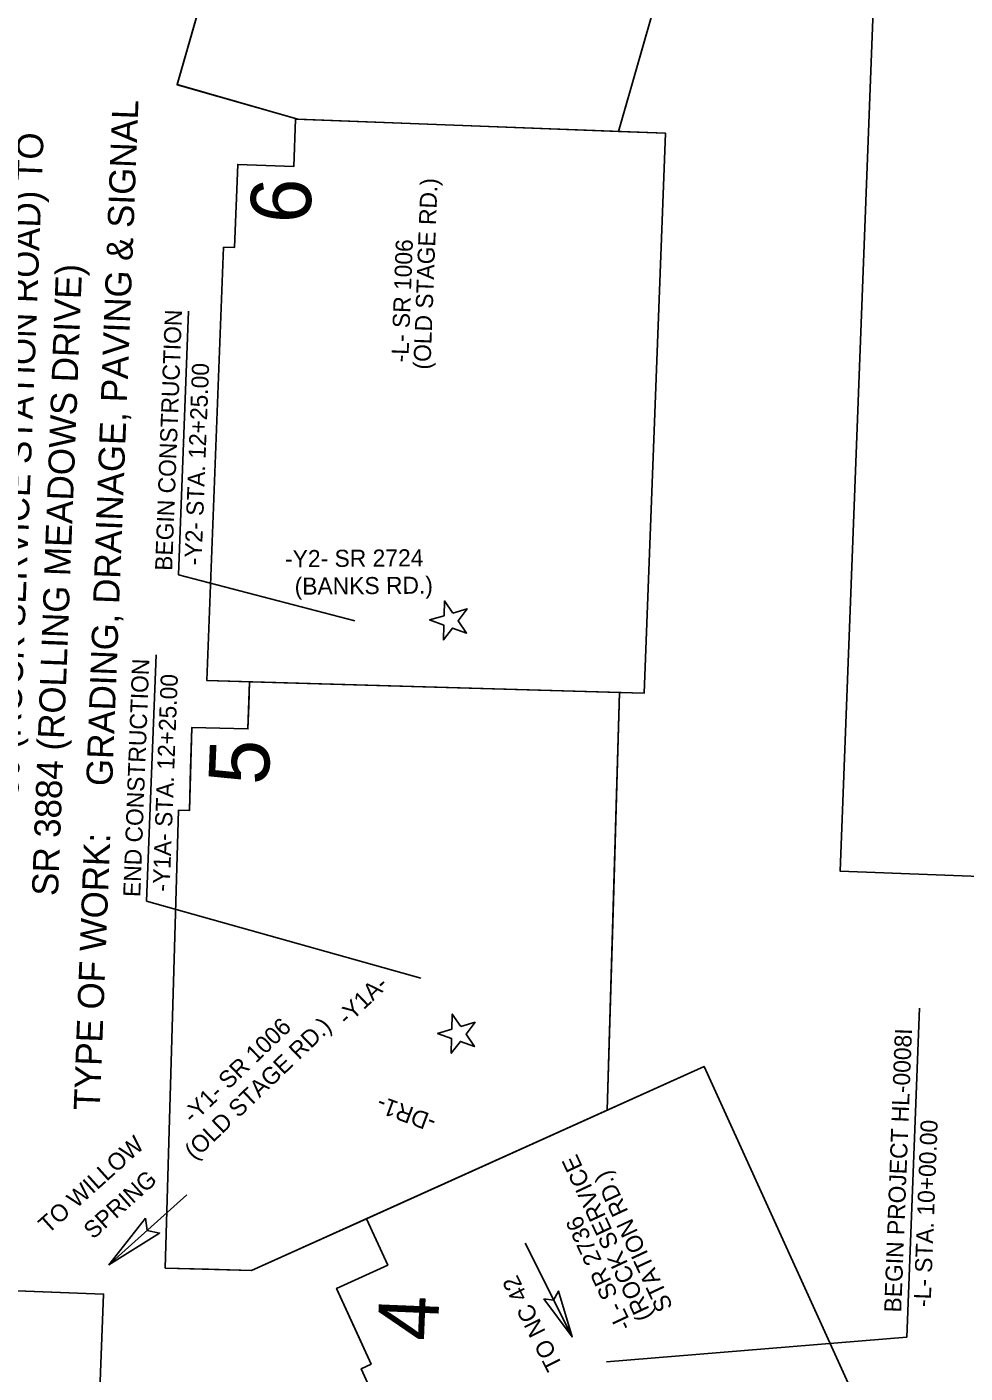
# Model space of a CAD drawing. Extents: x 1654773 to 2116434, y 680831 to 888488.
# Drawn here: x 2096697 to 2098950, y 685073 to 688306 of the extents above; entities that cross this region are included whole.
import ezdxf

# ---------------------------------------------------------------- set-up
doc = ezdxf.new("R2010")
doc.units = 0
for name, color, linetype in [('EC Title Sheet CELL', 7, 'Continuous'), ('Prop Horizontal Alignment', 7, 'Continuous'), ('Prop RDY Traffic Signal CELL', 7, 'Continuous'), ('Prop Terminator CELL', 7, 'Continuous'), ('Scratch_Level_3', 7, 'Continuous'), ('Sheet Data Field CELL', 7, 'Continuous'), ('Sheet Title CELL', 7, 'Continuous')]:
    doc.layers.add(name, color=color, linetype=linetype)

msp = doc.modelspace()

# ---------------------------------------------------------------- linework, layer by layer
at = {"layer": 'EC Title Sheet CELL'}
for points in [[(2098117.8, 688054.5), (2097347.7, 688084), (2097057.8, 688167), (2097360.5, 689224.4), (2097385.8, 689217.2), (2097440.8, 689409.5), (2097570.4, 689372.4), (2097625.5, 689564.8), (2098480.1, 689320.1)], [(2098179.2, 686705.4), (2097129.6, 686735.9), (2097169.5, 687776.6), (2097195.7, 687775.6), (2097203.4, 687975.5), (2097338.1, 687970.3), (2097342.5, 688084.2), (2098230.8, 688050.2)], [(2098090.8, 685704.4), (2097236.9, 685319), (2097029.4, 685325), (2097061.3, 686424.4), (2097087.6, 686423.7), (2097093.4, 686623.6), (2097228.1, 686619.7), (2097231.4, 686733), (2098120, 686707.2)], [(2098911.1, 684517.1), (2097955.4, 684082.2), (2097499.9, 685083.3), (2097523.8, 685094.2), (2097440.9, 685276.3), (2097563.6, 685332.1), (2097512.9, 685443.5), (2098323.2, 685809.3)]]:
    msp.add_lwpolyline(points, close=True, dxfattribs=at)
at = {"layer": 'Prop Horizontal Alignment'}
for p, q in [((2096894.2, 685332.8), (2097081.5, 685501.2)), ((2098006.4, 685159.8), (2097893.3, 685384.9))]:
    msp.add_line(p, q, dxfattribs=at)
at = {"layer": 'Prop RDY Traffic Signal CELL'}
for points in [[(2097720.1, 686897.8), (2097699.8, 686927.4), (2097698.8, 686891.6), (2097664.3, 686881.4), (2097698.2, 686869.3), (2097697.2, 686833.4), (2097719.1, 686861.9), (2097753, 686849.8), (2097732.7, 686879.5), (2097754.6, 686908), (2097720.1, 686897.8)], [(2097739, 685905.2), (2097718.7, 685934.8), (2097717.7, 685898.9), (2097683.2, 685888.7), (2097717.1, 685876.7), (2097716.1, 685840.7), (2097738, 685869.2), (2097771.9, 685857.1), (2097751.6, 685886.8), (2097773.5, 685915.3), (2097739, 685905.2)]]:
    msp.add_lwpolyline(points, dxfattribs=at)
at = {"layer": 'Prop Terminator CELL'}
for points in [[(2096982.3, 685444.9), (2096894.2, 685332.8), (2097015.8, 685408.9), (2096985.7, 685415.4)], [(2097938.4, 685251.4), (2098006.4, 685159.8), (2097973.3, 685269.7), (2097961.9, 685247.9)]]:
    msp.add_lwpolyline(points, close=True, dxfattribs=at)
at = {"layer": 'Scratch_Level_3'}
for points in [[(2096808.4, 683360), (2096881.4, 685262.6), (2096363.6, 685282.4), (2096507.8, 689043.2), (2096159.7, 689056.5), (2096216.4, 690534.7), (2098809.6, 690435.2), (2098650.1, 686277.9), (2099132, 686259.4), (2099018.8, 683308.3), (2099031.1, 683307.9), (2099030, 683278.9)], [(2094975.9, 683430.3), (2095048.9, 685332.8), (2096881.4, 685262.6), (2096808.4, 683360)]]:
    msp.add_lwpolyline(points, close=True, dxfattribs=at)
for points in [[(2097360.5, 689224.4), (2097058, 688167.4), (2097347.7, 688084), (2097342.5, 688084.2), (2097338.1, 687970.3), (2097203.4, 687975.5), (2097195.7, 687775.6), (2097169.5, 687776.6), (2097129.6, 686735.9), (2097231.4, 686733), (2097229.8, 686676.3), (2097228.1, 686619.7), (2097093.4, 686623.6), (2097090.5, 686523.6), (2097087.6, 686423.7), (2097061.3, 686424.4), (2097045.4, 685874.7), (2097029.4, 685325), (2097133.2, 685322), (2097236.9, 685319), (2097512.9, 685443.5), (2097563.6, 685332.1), (2097440.9, 685276.3), (2097482.4, 685185.3), (2097523.8, 685094.2), (2097499.9, 685083.3), (2097955.4, 684082.2)], [(2098911.1, 684517.1), (2098323.2, 685809.3), (2098090.8, 685704.4), (2098105.4, 686205.8), (2098120, 686707.2), (2098179.2, 686705.4), (2098205, 687377.8), (2098230.8, 688050.2), (2098117.8, 688054.5), (2098298.9, 688687.3)]]:
    msp.add_lwpolyline(points, dxfattribs=at)
at = {"layer": 'Sheet Data Field CELL'}
for p, q in [((2097061.3, 686989.6), (2097085.6, 687622.9)), ((2097485, 686879.6), (2097061.3, 686989.6)), ((2096984.8, 686206.1), (2097007.5, 686797.7)), ((2097643.4, 686021.5), (2096984.8, 686206.1)), ((2098809.9, 685159.4), (2098840.2, 685948.8)), ((2098809.9, 685159.4), (2098088.7, 685100.1))]:
    msp.add_line(p, q, dxfattribs=at)

# ---------------------------------------------------------------- texts
for s, height, rotation, p in [('GRADING, DRAINAGE, PAVING & SIGNAL', 62.69, 87.802, (2096902.1, 686481.7)), ('SR 2736 (ROCK SERVICE STATION ROAD) TO', 62.69, 87.802, (2096667.5, 686221.8)), ('(OLD STAGE RD.)', 41, 87.802, (2097666.1, 687482.3)), (' -L- SR 1006', 41, 87.802, (2097612.4, 687484.4)), ('SR 3884 (ROLLING MEADOWS DRIVE)', 62.69, 87.802, (2096771.9, 686217.8)), ('BEGIN CONSTRUCTION', 41, 87.802, (2097045.9, 686999)), ('-Y2- STA. 12+25.00', 41, 87.802, (2097116.4, 687012.1)), ('-Y2- SR 2724 ', 41, 0.4489, (2097317.3, 687007.9)), ('(BANKS RD.)', 41, 0.4489, (2097340.3, 686942.1)), ('END CONSTRUCTION', 41, 87.802, (2096969.4, 686215.5)), ('-Y1A- STA. 12+25.00', 41, 87.802, (2097039.9, 686228.6)), ('-Y1A- ', 41, 43.8747, (2097466.4, 685905.7)), ('(OLD STAGE RD.)', 41, 43.8747, (2097100, 685582.6)), ('-Y1- SR 1006', 41, 43.8747, (2097095.5, 685670)), ('BEGIN PROJECT HL-0008I', 41, 87.802, (2098796.4, 685217.8)), ('-DR1-', 41, 159.7092, (2097683.4, 685689.3)), ('-L- STA. 10+00.00', 41, 87.802, (2098867, 685231)), ('TO WILLOW', 41, 41.9465, (2096748.3, 685405.7)), (' (ROCK SERVICE', 41, 115.0722, (2098207, 685195.3)), ('SPRING', 41, 41.9465, (2096856.4, 685392.5)), (' STATION RD.)', 41, 115.0722, (2098255.7, 685218.1)), (' -L- SR 2736 ', 41, 115.0722, (2098158.3, 685172.5)), ('TO NC 42', 41, 116.6828, (2097984.7, 685090.5))]:
    msp.add_text(s, height=height, rotation=rotation, dxfattribs=at).set_placement(p)
at = {"layer": 'Sheet Title CELL'}
for s, height, rotation, p in [('6', 144.6, 87.6347, (2097377.3, 687831.9)), ('5', 144.6, 87.6347, (2097277.4, 686484)), ('TYPE OF WORK:', 62.69, 87.802, (2096872.2, 685702.9)), ('4', 144.6, 87.6347, (2097683.2, 685148.7))]:
    msp.add_text(s, height=height, rotation=rotation, dxfattribs=at).set_placement(p)

doc.saveas('drawing.dxf')
